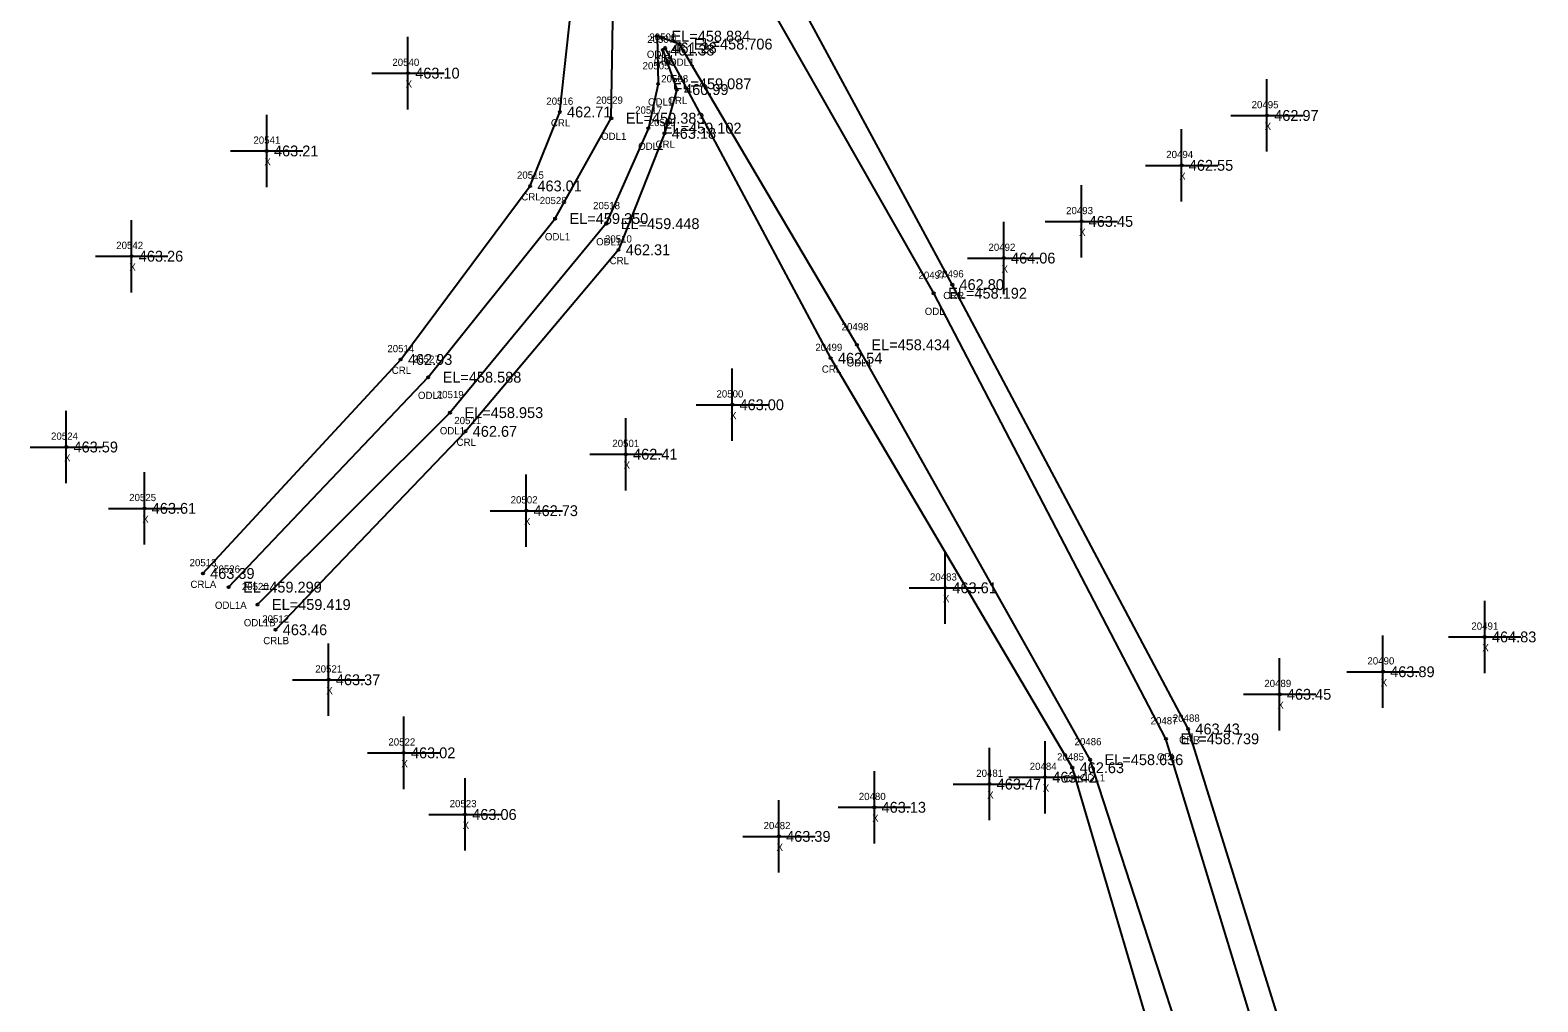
# Model space of a CAD drawing. Extents: x 1785066 to 1786589, y 770293 to 771312.
# Drawn here: x 1785788 to 1785996.3, y 770448 to 770582.3 of the extents above; entities that cross this region are included whole.
import ezdxf

# ---------------------------------------------------------------- set-up
doc = ezdxf.new("R2010")
doc.units = 0
for name, color, linetype in [('RD_EX_H2O', 7, 'Continuous'), ('RD_EX_H2O_txCode', 7, 'Continuous'), ('RD_EX_Misc', 7, 'Continuous'), ('RD_EX_Misc_txCode', 7, 'Continuous'), ('RD_EX_TX_H2O_ELEV', 7, 'Continuous'), ('RD_EX_TX_Misc_ELEV', 7, 'Continuous'), ('RD_SMD_Locator', 7, 'Continuous')]:
    doc.layers.add(name, color=color, linetype=linetype)

msp = doc.modelspace()

# ---------------------------------------------------------------- linework, layer by layer
at = {"layer": 'RD_EX_H2O'}
for points in [[(1785811.86, 770507.25), (1785839.19, 770536.83), (1785857.09, 770560.81), (1785861.18, 770571.03), (1785863.41, 770591.28), (1785864.16, 770601.21), (1785851.56, 770633.71), (1785810.97, 770676.91), (1785806.98, 770721.47), (1785793.39, 770786.72), (1785796.81, 770824.03), (1785795.63, 770828.98)], [(1785996.34, 770328.69), (1785988.37, 770343.77), (1785978.71, 770369.85), (1785965.55, 770429.48), (1785948.02, 770485.76), (1785915.42, 770547.17), (1785885.85, 770601.99), (1785867.88, 770639.76), (1785836.38, 770688.5), (1785826.2, 770733.3), (1785818.95, 770788.69), (1785812.88, 770814.19), (1785823.4, 770822.64)], [(1785815.41, 770505.36), (1785842.99, 770534.37), (1785860.53, 770556.3), (1785868.3, 770570.17), (1785868.62, 770589.11), (1785869.97, 770602.61), (1785853.21, 770635.68), (1785818.18, 770678.49), (1785809.1, 770721.92), (1785797.13, 770787.08)], [(1785994.72, 770327.79), (1785985.4, 770344.24), (1785977.02, 770368.92), (1785961.9, 770428.77), (1785944.95, 770484.4), (1785912.86, 770545.98), (1785881.75, 770600.7), (1785866.13, 770637.95), (1785834.03, 770687.39), (1785820.66, 770730.64), (1785814.87, 770787.58)], [(1785985.94, 770320.75), (1785972.57, 770331.88), (1785965.29, 770366.66), (1785953.01, 770424.56), (1785934.47, 770481.51), (1785902.24, 770538.86), (1785877.7, 770580.42), (1785874.62, 770581.51), (1785874.78, 770574.93), (1785873.42, 770568.8), (1785867.61, 770555.6), (1785846.01, 770529.48), (1785819.4, 770502.95)], [(1785981.47, 770318.52), (1785965.36, 770326.44), (1785962.76, 770365.76), (1785948.86, 770423.41), (1785932.02, 770480.4), (1785898.62, 770537), (1785875.74, 770579.89), (1785875.42, 770579.59), (1785877.36, 770574.13), (1785875.64, 770568.08), (1785869.3, 770551.99), (1785848.15, 770526.89), (1785821.9, 770499.47)]]:
    msp.add_lwpolyline(points, dxfattribs=at)
at = {"layer": 'RD_EX_Misc'}
for p, q in [((1785840.2, 770571.4), (1785840.2, 770581.4)), ((1785835.2, 770576.4), (1785845.2, 770576.4)), ((1785958.91, 770565.55), (1785958.91, 770575.55)), ((1785820.68, 770560.65), (1785820.68, 770570.65)), ((1785953.91, 770570.55), (1785963.91, 770570.55)), ((1785947.11, 770558.66), (1785947.11, 770568.66)), ((1785815.68, 770565.65), (1785825.68, 770565.65)), ((1785942.11, 770563.66), (1785952.11, 770563.66)), ((1785933.27, 770550.91), (1785933.27, 770560.91)), ((1785802, 770546.1), (1785802, 770556.1)), ((1785922.54, 770545.84), (1785922.54, 770555.84)), ((1785928.27, 770555.91), (1785938.27, 770555.91)), ((1785797, 770551.1), (1785807, 770551.1)), ((1785917.54, 770550.84), (1785927.54, 770550.84)), ((1785885.02, 770525.57), (1785885.02, 770535.57)), ((1785792.98, 770519.73), (1785792.98, 770529.73)), ((1785880.02, 770530.57), (1785890.02, 770530.57)), ((1785870.31, 770518.73), (1785870.31, 770528.73)), ((1785787.98, 770524.73), (1785797.98, 770524.73)), ((1785865.31, 770523.73), (1785875.31, 770523.73)), ((1785803.79, 770511.25), (1785803.79, 770521.25)), ((1785856.55, 770510.93), (1785856.55, 770520.93)), ((1785798.79, 770516.25), (1785808.79, 770516.25)), ((1785851.55, 770515.93), (1785861.55, 770515.93)), ((1785914.44, 770500.27), (1785914.44, 770510.27)), ((1785909.44, 770505.27), (1785919.44, 770505.27)), ((1785989, 770493.48), (1785989, 770503.48)), ((1785974.94, 770488.67), (1785974.94, 770498.67)), ((1785984, 770498.48), (1785994, 770498.48)), ((1785829.23, 770487.56), (1785829.23, 770497.56)), ((1785960.66, 770485.55), (1785960.66, 770495.55)), ((1785824.23, 770492.56), (1785834.23, 770492.56)), ((1785969.94, 770493.67), (1785979.94, 770493.67)), ((1785955.66, 770490.55), (1785965.66, 770490.55)), ((1785839.61, 770477.46), (1785839.61, 770487.46)), ((1785928.24, 770474.09), (1785928.24, 770484.09)), ((1785834.61, 770482.46), (1785844.61, 770482.46)), ((1785920.56, 770473.14), (1785920.56, 770483.14)), ((1785904.65, 770469.93), (1785904.65, 770479.93)), ((1785848.08, 770468.94), (1785848.08, 770478.94)), ((1785915.56, 770478.14), (1785925.56, 770478.14)), ((1785923.24, 770479.09), (1785933.24, 770479.09)), ((1785891.46, 770465.91), (1785891.46, 770475.91)), ((1785843.08, 770473.94), (1785853.08, 770473.94)), ((1785899.65, 770474.93), (1785909.65, 770474.93)), ((1785886.46, 770470.91), (1785896.46, 770470.91))]:
    msp.add_line(p, q, dxfattribs=at)
at = {"layer": 'RD_SMD_Locator'}
for centre in [(1785874.62, 770581.51), (1785875.42, 770579.59), (1785875.74, 770579.89), (1785877.7, 770580.42), (1785840.2, 770576.4), (1785874.78, 770574.93), (1785877.36, 770574.13), (1785861.18, 770571.03), (1785868.3, 770570.17), (1785958.91, 770570.55), (1785873.42, 770568.8), (1785875.64, 770568.08), (1785820.68, 770565.65), (1785947.11, 770563.66), (1785857.09, 770560.81), (1785860.53, 770556.3), (1785867.61, 770555.6), (1785933.27, 770555.91), (1785802, 770551.1), (1785869.3, 770551.99), (1785922.54, 770550.84), (1785915.42, 770547.17), (1785912.86, 770545.98), (1785902.24, 770538.86), (1785839.19, 770536.83), (1785898.62, 770537), (1785842.99, 770534.37), (1785846.01, 770529.48), (1785885.02, 770530.57), (1785848.15, 770526.89), (1785792.98, 770524.73), (1785870.31, 770523.73), (1785803.79, 770516.25), (1785856.55, 770515.93), (1785811.86, 770507.25), (1785815.41, 770505.36), (1785914.44, 770505.27), (1785819.4, 770502.95), (1785821.9, 770499.47), (1785989, 770498.48), (1785829.23, 770492.56), (1785974.94, 770493.67), (1785960.66, 770490.55), (1785948.02, 770485.76), (1785944.95, 770484.4), (1785839.61, 770482.46), (1785934.47, 770481.51), (1785932.02, 770480.4), (1785920.56, 770478.14), (1785928.24, 770479.09), (1785848.08, 770473.94), (1785904.65, 770474.93), (1785891.46, 770470.91)]:
    msp.add_circle(centre, 0.15, dxfattribs=at)

# ---------------------------------------------------------------- texts
at = {"layer": 'RD_EX_H2O_txCode'}
for s, p in [('20507', (1785873.26, 770580.59)), ('20506', (1785873.56, 770580.89)), ('ODL1', (1785873.21, 770578.51)), ('20505', (1785872.62, 770576.93)), ('CRL', (1785874.19, 770577.59)), ('CRL', (1785874.51, 770577.89)), ('ODL1', (1785876.29, 770577.42)), ('20508', (1785875.2, 770575.13)), ('20516', (1785859.32, 770572.03)), ('20529', (1785866.18, 770572.17)), ('20517', (1785871.59, 770570.8)), ('ODL1', (1785873.37, 770571.93)), ('CRL', (1785876.13, 770572.13)), ('CRL', (1785859.95, 770569.03)), ('20509', (1785873.48, 770569.08)), ('ODL1', (1785866.89, 770567.17)), ('CRL', (1785874.41, 770566.08)), ('ODL1', (1785872.01, 770565.8)), ('20515', (1785855.26, 770561.81)), ('CRL', (1785855.86, 770558.81)), ('20528', (1785858.41, 770558.3)), ('20518', (1785865.78, 770557.6)), ('ODL1', (1785859.12, 770553.3)), ('ODL1', (1785866.2, 770552.6)), ('20510', (1785867.42, 770552.99)), ('CRL', (1785868.07, 770549.99)), ('20497', (1785910.75, 770547.98)), ('20496', (1785913.28, 770548.17)), ('CRR', (1785914.17, 770545.17)), ('ODL', (1785911.62, 770542.98)), ('20498', (1785900.13, 770540.86)), ('20514', (1785837.35, 770537.83)), ('20499', (1785896.5, 770538)), ('CRL', (1785837.96, 770534.83)), ('20527', (1785840.87, 770536.37)), ('CRL', (1785897.39, 770535)), ('ODL1', (1785900.83, 770535.86)), ('ODL1', (1785841.58, 770531.37)), ('20519', (1785844.18, 770531.48)), ('ODL1', (1785844.6, 770526.48)), ('20511', (1785846.6, 770527.89)), ('CRL', (1785846.92, 770524.89)), ('20513', (1785810.02, 770508.25)), ('20526', (1785813.27, 770507.36)), ('CRLA', (1785810.14, 770505.25)), ('20520', (1785817.24, 770504.95)), ('ODL1A', (1785813.52, 770502.36)), ('ODL1B', (1785817.51, 770499.95)), ('20512', (1785820.06, 770500.47)), ('CRLB', (1785820.2, 770497.47)), ('20487', (1785942.83, 770486.4)), ('20488', (1785945.9, 770486.76)), ('20486', (1785932.32, 770483.51)), ('CRR', (1785946.76, 770483.76)), ('20485', (1785929.9, 770481.4)), ('ODL', (1785943.7, 770481.4)), ('ODL1', (1785933.06, 770478.51)), ('CRL', (1785930.79, 770478.4))]:
    msp.add_text(s, height=1, dxfattribs=at).set_placement(p)
at = {"layer": 'RD_EX_Misc_txCode'}
for s, p in [('20540', (1785838.04, 770577.4)), ('X', (1785839.88, 770574.4)), ('20495', (1785956.79, 770571.55)), ('X', (1785958.59, 770568.55)), ('20541', (1785818.84, 770566.65)), ('20494', (1785944.99, 770564.66)), ('X', (1785820.36, 770563.65)), ('X', (1785946.79, 770561.66)), ('20493', (1785931.15, 770556.91)), ('X', (1785932.95, 770553.91)), ('20542', (1785799.88, 770552.1)), ('20492', (1785920.42, 770551.84)), ('X', (1785801.69, 770549.1)), ('X', (1785922.23, 770548.84)), ('20500', (1785882.83, 770531.57)), ('X', (1785884.71, 770528.57)), ('20524', (1785790.87, 770525.73)), ('20501', (1785868.44, 770524.73)), ('X', (1785792.67, 770522.73)), ('X', (1785870, 770521.73)), ('20525', (1785801.67, 770517.25)), ('20502', (1785854.39, 770516.93)), ('X', (1785803.48, 770514.25)), ('X', (1785856.24, 770513.93)), ('20483', (1785912.33, 770506.27)), ('X', (1785914.13, 770503.27)), ('20491', (1785987.16, 770499.48)), ('X', (1785988.68, 770496.48)), ('20521', (1785827.39, 770493.56)), ('20490', (1785972.79, 770494.67)), ('20489', (1785958.54, 770491.55)), ('X', (1785974.63, 770491.67)), ('X', (1785828.91, 770490.56)), ('X', (1785960.35, 770488.55)), ('20522', (1785837.49, 770483.46)), ('X', (1785839.29, 770480.46)), ('20481', (1785918.73, 770479.14)), ('20484', (1785926.12, 770480.09)), ('X', (1785927.92, 770477.09)), ('20523', (1785845.96, 770474.94)), ('20480', (1785902.5, 770475.93)), ('X', (1785920.25, 770476.14)), ('X', (1785904.34, 770472.93)), ('X', (1785847.76, 770471.94)), ('20482', (1785889.34, 770471.91)), ('X', (1785891.14, 770468.91))]:
    msp.add_text(s, height=1, dxfattribs=at).set_placement(p)
at = {"layer": 'RD_EX_TX_H2O_ELEV'}
for s, p in [('EL=458.884', (1785876.62, 770580.76)), ('461.38', (1785876.42, 770578.84)), ('461.28', (1785876.74, 770579.14)), ('EL=458.706', (1785879.7, 770579.67)), ('EL=459.087', (1785876.78, 770574.18)), ('460.99', (1785878.36, 770573.38)), ('462.71', (1785862.18, 770570.28)), ('EL=459.383', (1785870.3, 770569.42)), ('EL=459.102', (1785875.42, 770568.05)), ('463.18', (1785876.64, 770567.33)), ('463.01', (1785858.09, 770560.06)), ('EL=459.350', (1785862.53, 770555.55)), ('EL=459.448', (1785869.61, 770554.85)), ('462.31', (1785870.3, 770551.24)), ('EL=458.192', (1785914.86, 770545.23)), ('462.80', (1785916.42, 770546.42)), ('EL=458.434', (1785904.24, 770538.11)), ('462.93', (1785840.19, 770536.08)), ('462.54', (1785899.62, 770536.25)), ('EL=458.588', (1785844.99, 770533.62)), ('EL=458.953', (1785848.01, 770528.73)), ('462.67', (1785849.15, 770526.14)), ('463.39', (1785812.86, 770506.5)), ('EL=459.299', (1785817.41, 770504.61)), ('EL=459.419', (1785821.4, 770502.2)), ('463.46', (1785822.9, 770498.72)), ('463.43', (1785949.02, 770485.01)), ('EL=458.739', (1785946.95, 770483.65)), ('EL=458.636', (1785936.47, 770480.76)), ('462.63', (1785933.02, 770479.65))]:
    msp.add_text(s, height=1.5, dxfattribs=at).set_placement(p)
at = {"layer": 'RD_EX_TX_Misc_ELEV'}
for s, p in [('463.10', (1785841.2, 770575.65)), ('462.97', (1785959.91, 770569.8)), ('463.21', (1785821.68, 770564.9)), ('462.55', (1785948.11, 770562.91)), ('463.45', (1785934.27, 770555.16)), ('463.26', (1785803, 770550.35)), ('464.06', (1785923.54, 770550.09)), ('463.00', (1785886.02, 770529.82)), ('463.59', (1785793.98, 770523.98)), ('462.41', (1785871.31, 770522.98)), ('463.61', (1785804.79, 770515.5)), ('462.73', (1785857.55, 770515.18)), ('463.61', (1785915.44, 770504.52)), ('464.83', (1785990, 770497.73)), ('463.89', (1785975.94, 770492.92)), ('463.37', (1785830.23, 770491.81)), ('463.45', (1785961.66, 770489.8)), ('463.02', (1785840.61, 770481.71)), ('463.42', (1785929.24, 770478.34)), ('463.47', (1785921.56, 770477.39)), ('463.13', (1785905.65, 770474.18)), ('463.06', (1785849.08, 770473.19)), ('463.39', (1785892.46, 770470.16))]:
    msp.add_text(s, height=1.5, dxfattribs=at).set_placement(p)

doc.saveas('drawing.dxf')
